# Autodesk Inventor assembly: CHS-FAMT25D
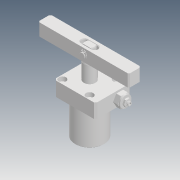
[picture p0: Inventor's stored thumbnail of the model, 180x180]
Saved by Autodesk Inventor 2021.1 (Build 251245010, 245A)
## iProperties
Created: 2019-05
Part Number: CHS-FAMT25D
Description: STEP AP203
Document SubType Name: Assembly
Designer: user
Title: chs-famt25d_asm.STEP
Revision Number: ÈÎºÎ
Sending System: SolidWorks 2017
Preprocessor: SwSTEP 2.0
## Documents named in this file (9)
- D:\Vault_2016\Projekty\Clamptek\Hydraulic\CHS\CHS-25\Inventor\CHS-FAMT25D\CHS-FAMT25D.iam
- D:\Vault_2016\Projekty\Clamptek\Hydraulic\CHS\CHS-25\Inventor\CHS-FAMT25D\CHS-25D-02_3.ipt
- D:\Vault_2016\Projekty\Clamptek\Hydraulic\CHS\CHS-25\Inventor\CHS-FAMT25D\CHS-25D-01_3.ipt
- D:\Vault_2016\Projekty\Clamptek\Hydraulic\CHS\CHS-25\Inventor\CHS-FAMT25D\Xiao.ipt
- D:\Vault_2016\Projekty\Clamptek\Hydraulic\CHS\CHS-25\Inventor\CHS-FAMT25D\Öá8µ²È¦.ipt
- D:\Vault_2016\Projekty\Clamptek\Hydraulic\CHS\CHS-25\Inventor\CHS-FAMT25D\20·§Ìå_1.ipt
- D:\Vault_2016\Projekty\Clamptek\Hydraulic\CHS\CHS-25\Inventor\CHS-FAMT25D\20µ÷ËÙ¸Ë_1.ipt
- D:\Vault_2016\Projekty\Clamptek\Hydraulic\CHS\CHS-25\Inventor\CHS-FAMT25D\hex thin nuts-grades ab-chamfered gb(GB_FASTENER_NUT_STNAB M6-S)_1.ipt
- D:\Vault_2016\Projekty\Clamptek\Hydraulic\CHS\CHS-25\Inventor\CHS-FAMT25D\CHS-FAMT25BT_1.ipt
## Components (9 placed, 9 different names)
1. CHS-25D-02_3_1
2. CHS-25D-01_3_2
3. Xiao_3
4. Öá8µ²È¦_4
5. Öá8µ²È¦_5
6. 20·§Ìå_1_6
7. 20µ÷ËÙ¸Ë_1_7
8. hex thin nuts-grades ab-chamfered gb(GB_FASTENER_NUT_STNAB M6-S)_1_8
9. CHS-FAMT25BT_1_9
